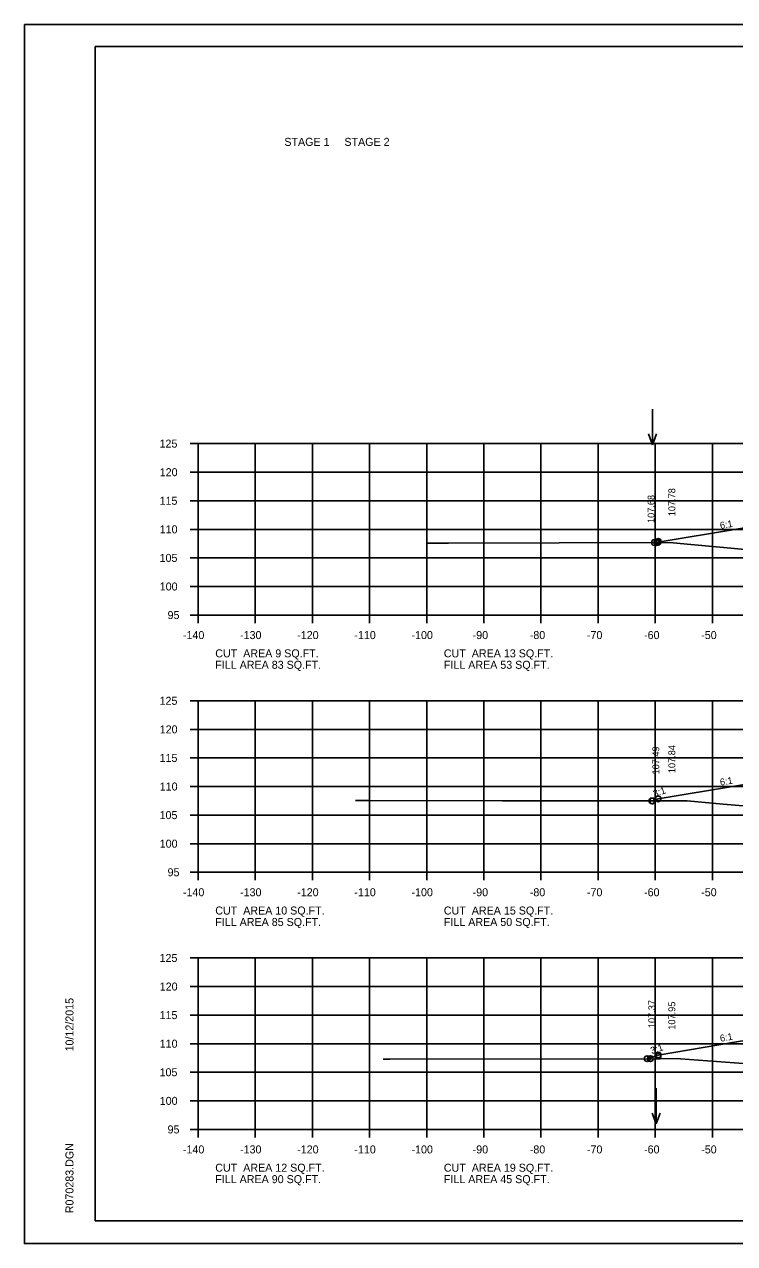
# Model space of a CAD drawing. Extents: x 1175611 to 1176402, y -433344 to -416213.
# Drawn here: x 1175610.6 to 1175734.9, y -428223.4 to -428010.1 of the extents above; entities that cross this region are included whole.
import ezdxf

# ---------------------------------------------------------------- set-up
doc = ezdxf.new("R2010")
doc.units = 0
for name, color, linetype in [('Default', 7, 'Continuous'), ('R_Axis', 7, 'Continuous'), ('R_Axis Annot', 7, 'Continuous'), ('R_Border', 7, 'Continuous'), ('R_Exist Surface', 7, 'Continuous'), ('R_Fin Surface', 7, 'Continuous'), ('R_Grid', 7, 'Continuous'), ('R_No Plot', 7, 'Continuous'), ('R_Water Annot', 7, 'Continuous'), ('R_Xsect Elev', 7, 'Continuous'), ('R_Xsect Slope', 7, 'Continuous')]:
    doc.layers.add(name, color=color, linetype=linetype)

msp = doc.modelspace()

# ---------------------------------------------------------------- linework, layer by layer
at = {"layer": 'R_Axis'}
for p, q in [((1175639.57, -428083.44), (1175640.97, -428083.44)), ((1175640.97, -428113.44), (1175640.97, -428083.44)), ((1175639.57, -428088.44), (1175640.97, -428088.44)), ((1175639.57, -428093.44), (1175640.97, -428093.44)), ((1175639.57, -428098.44), (1175640.97, -428098.44)), ((1175639.57, -428103.44), (1175640.97, -428103.44)), ((1175639.57, -428108.44), (1175640.97, -428108.44)), ((1175639.57, -428113.44), (1175640.97, -428113.44)), ((1175640.97, -428113.44), (1175920.97, -428113.44)), ((1175640.97, -428114.84), (1175640.97, -428113.44)), ((1175650.97, -428114.84), (1175650.97, -428113.44)), ((1175660.97, -428114.84), (1175660.97, -428113.44)), ((1175670.97, -428114.84), (1175670.97, -428113.44)), ((1175680.97, -428114.84), (1175680.97, -428113.44)), ((1175690.97, -428114.84), (1175690.97, -428113.44)), ((1175700.97, -428114.84), (1175700.97, -428113.44)), ((1175710.97, -428114.84), (1175710.97, -428113.44)), ((1175720.97, -428114.84), (1175720.97, -428113.44)), ((1175730.97, -428114.84), (1175730.97, -428113.44)), ((1175639.57, -428128.44), (1175640.97, -428128.44)), ((1175640.97, -428158.44), (1175640.97, -428128.44)), ((1175639.57, -428133.44), (1175640.97, -428133.44)), ((1175639.57, -428138.44), (1175640.97, -428138.44)), ((1175639.57, -428143.44), (1175640.97, -428143.44)), ((1175639.57, -428148.44), (1175640.97, -428148.44)), ((1175639.57, -428153.44), (1175640.97, -428153.44)), ((1175639.57, -428158.44), (1175640.97, -428158.44)), ((1175640.97, -428158.44), (1175920.97, -428158.44)), ((1175640.97, -428159.84), (1175640.97, -428158.44)), ((1175650.97, -428159.84), (1175650.97, -428158.44)), ((1175660.97, -428159.84), (1175660.97, -428158.44)), ((1175670.97, -428159.84), (1175670.97, -428158.44)), ((1175680.97, -428159.84), (1175680.97, -428158.44)), ((1175690.97, -428159.84), (1175690.97, -428158.44)), ((1175700.97, -428159.84), (1175700.97, -428158.44)), ((1175710.97, -428159.84), (1175710.97, -428158.44)), ((1175720.97, -428159.84), (1175720.97, -428158.44)), ((1175730.97, -428159.84), (1175730.97, -428158.44)), ((1175639.57, -428173.44), (1175640.97, -428173.44)), ((1175640.97, -428203.44), (1175640.97, -428173.44)), ((1175639.57, -428178.44), (1175640.97, -428178.44)), ((1175639.57, -428183.44), (1175640.97, -428183.44)), ((1175639.57, -428188.44), (1175640.97, -428188.44)), ((1175639.57, -428193.44), (1175640.97, -428193.44)), ((1175639.57, -428198.44), (1175640.97, -428198.44)), ((1175639.57, -428203.44), (1175640.97, -428203.44)), ((1175640.97, -428203.44), (1175920.97, -428203.44)), ((1175640.97, -428204.84), (1175640.97, -428203.44)), ((1175650.97, -428204.84), (1175650.97, -428203.44)), ((1175660.97, -428204.84), (1175660.97, -428203.44)), ((1175670.97, -428204.84), (1175670.97, -428203.44)), ((1175680.97, -428204.84), (1175680.97, -428203.44)), ((1175690.97, -428204.84), (1175690.97, -428203.44)), ((1175700.97, -428204.84), (1175700.97, -428203.44)), ((1175710.97, -428204.84), (1175710.97, -428203.44)), ((1175720.97, -428204.84), (1175720.97, -428203.44)), ((1175730.97, -428204.84), (1175730.97, -428203.44))]:
    msp.add_line(p, q, dxfattribs=at)
at = {"layer": 'R_Border'}
for p, q in [((1175622.97, -428013.98), (1175939.15, -428013.98)), ((1175622.97, -428219.44), (1175622.97, -428013.98)), ((1175622.97, -428219.44), (1175622.97, -428219.44)), ((1175939.15, -428219.44), (1175622.97, -428219.44))]:
    msp.add_line(p, q, dxfattribs=at)
at = {"layer": 'R_Exist Surface'}
for points in [[(1175680.97, -428100.86), (1175683.75, -428100.86), (1175683.81, -428100.86), (1175684.78, -428100.85), (1175723.5, -428100.76), (1175726.54, -428101.03), (1175737.33, -428102)], [(1175668.53, -428145.86), (1175669.76, -428145.87), (1175670.85, -428145.87), (1175694.26, -428145.92), (1175726.57, -428145.95), (1175732.83, -428146.53), (1175738.48, -428147.02)], [(1175673.33, -428191.17), (1175673.85, -428191.17), (1175674.52, -428191.17), (1175721.8, -428191.06), (1175724.8, -428191.05), (1175725.38, -428191.09), (1175739.54, -428192.12)]]:
    msp.add_lwpolyline(points, dxfattribs=at)
at = {"layer": 'R_Fin Surface'}
for points in [[(1175721.26, -428100.76), (1175721.47, -428100.69), (1175735.2, -428098.4), (1175743.47, -428097.03), (1175749.47, -428096.79), (1175751.47, -428096.75), (1175780.97, -428096.16), (1175810.47, -428096.75), (1175812.47, -428096.79), (1175818.47, -428097.03), (1175823.75, -428098.34), (1175840.45, -428102.32), (1175844.7, -428101.12)], [(1175720.47, -428145.95), (1175721.47, -428145.61), (1175735.2, -428143.32), (1175743.47, -428141.94), (1175749.47, -428141.7), (1175751.47, -428141.66), (1175780.97, -428141.07), (1175810.47, -428141.66), (1175812.47, -428141.7), (1175818.47, -428141.94), (1175823.75, -428143.26), (1175840.47, -428147.44), (1175844.79, -428146.01)], [(1175719.55, -428191.06), (1175721.47, -428190.42), (1175735.2, -428188.14), (1175743.47, -428186.76), (1175749.47, -428186.52), (1175751.47, -428186.48), (1175780.97, -428185.89), (1175810.47, -428186.48), (1175812.47, -428186.52), (1175818.47, -428186.76), (1175823.75, -428188.08), (1175840.47, -428192.26), (1175841.18, -428192.49), (1175845.12, -428191.18)]]:
    msp.add_lwpolyline(points, dxfattribs=at)
at = {"layer": 'R_Grid'}
for p, q in [((1175640.97, -428083.44), (1175920.97, -428083.44)), ((1175640.97, -428113.44), (1175640.97, -428083.44)), ((1175650.97, -428113.44), (1175650.97, -428083.44)), ((1175660.97, -428113.44), (1175660.97, -428083.44)), ((1175670.97, -428113.44), (1175670.97, -428083.44)), ((1175680.97, -428113.44), (1175680.97, -428083.44)), ((1175690.97, -428113.44), (1175690.97, -428083.44)), ((1175700.97, -428113.44), (1175700.97, -428083.44)), ((1175710.97, -428113.44), (1175710.97, -428083.44)), ((1175720.97, -428113.44), (1175720.97, -428083.44)), ((1175730.97, -428113.44), (1175730.97, -428083.44)), ((1175640.97, -428088.44), (1175920.97, -428088.44)), ((1175640.97, -428093.44), (1175920.97, -428093.44)), ((1175640.97, -428098.44), (1175920.97, -428098.44)), ((1175640.97, -428103.44), (1175920.97, -428103.44)), ((1175640.97, -428108.44), (1175920.97, -428108.44)), ((1175640.97, -428113.44), (1175920.97, -428113.44)), ((1175640.97, -428128.44), (1175920.97, -428128.44)), ((1175640.97, -428158.44), (1175640.97, -428128.44)), ((1175650.97, -428158.44), (1175650.97, -428128.44)), ((1175660.97, -428158.44), (1175660.97, -428128.44)), ((1175670.97, -428158.44), (1175670.97, -428128.44)), ((1175680.97, -428158.44), (1175680.97, -428128.44)), ((1175690.97, -428158.44), (1175690.97, -428128.44)), ((1175700.97, -428158.44), (1175700.97, -428128.44)), ((1175710.97, -428158.44), (1175710.97, -428128.44)), ((1175720.97, -428158.44), (1175720.97, -428128.44)), ((1175730.97, -428158.44), (1175730.97, -428128.44)), ((1175640.97, -428133.44), (1175920.97, -428133.44)), ((1175640.97, -428138.44), (1175920.97, -428138.44)), ((1175640.97, -428143.44), (1175920.97, -428143.44)), ((1175640.97, -428148.44), (1175920.97, -428148.44)), ((1175640.97, -428153.44), (1175920.97, -428153.44)), ((1175640.97, -428158.44), (1175920.97, -428158.44)), ((1175640.97, -428173.44), (1175920.97, -428173.44)), ((1175640.97, -428203.44), (1175640.97, -428173.44)), ((1175650.97, -428203.44), (1175650.97, -428173.44)), ((1175660.97, -428203.44), (1175660.97, -428173.44)), ((1175670.97, -428203.44), (1175670.97, -428173.44)), ((1175680.97, -428203.44), (1175680.97, -428173.44)), ((1175690.97, -428203.44), (1175690.97, -428173.44)), ((1175700.97, -428203.44), (1175700.97, -428173.44)), ((1175710.97, -428203.44), (1175710.97, -428173.44)), ((1175720.97, -428203.44), (1175720.97, -428173.44)), ((1175730.97, -428203.44), (1175730.97, -428173.44)), ((1175640.97, -428178.44), (1175920.97, -428178.44)), ((1175640.97, -428183.44), (1175920.97, -428183.44)), ((1175640.97, -428188.44), (1175920.97, -428188.44)), ((1175640.97, -428193.44), (1175920.97, -428193.44)), ((1175640.97, -428198.44), (1175920.97, -428198.44)), ((1175640.97, -428203.44), (1175920.97, -428203.44))]:
    msp.add_line(p, q, dxfattribs=at)
at = {"layer": 'R_No Plot'}
for p, q in [((1175610.57, -428010.08), (1175943.91, -428010.08)), ((1175610.57, -428223.42), (1175943.91, -428223.42))]:
    msp.add_line(p, q, dxfattribs=at)
msp.add_lwpolyline([(1175610.57, -428010.08), (1175943.91, -428010.08), (1175943.91, -428223.42), (1175610.57, -428223.42)], close=True, dxfattribs=at)
for centre in [(1175720.81, -428100.76), (1175721.26, -428100.76), (1175721.26, -428100.76), (1175721.47, -428100.54), (1175721.47, -428100.69), (1175721.47, -428145.58), (1175720.36, -428145.95), (1175720.47, -428145.95), (1175720.47, -428145.95), (1175721.47, -428145.61), (1175719.55, -428191.06), (1175719.55, -428191.06), (1175720.11, -428191.06), (1175721.47, -428190.42), (1175721.47, -428190.61)]:
    msp.add_circle(centre, 0.5, dxfattribs=at)
at = {"layer": 'R_Water Annot'}
for p, q in [((1175720.5, -428077.39), (1175720.5, -428083.67)), ((1175720.5, -428083.67), (1175719.8, -428081.75)), ((1175720.5, -428083.67), (1175721.2, -428081.75)), ((1175721.12, -428196.21), (1175721.12, -428202.49)), ((1175721.12, -428202.49), (1175720.42, -428200.57)), ((1175721.12, -428202.49), (1175721.82, -428200.57))]:
    msp.add_line(p, q, dxfattribs=at)

# ---------------------------------------------------------------- texts
at = {"layer": 'Default'}
for s, p in [('STAGE 1     STAGE 2', (1175656.06, -428031.34)), ('CUT  AREA 9 SQ.FT.', (1175643.97, -428120.84)), ('CUT  AREA 13 SQ.FT.', (1175683.97, -428120.84)), ('FILL AREA 83 SQ.FT.', (1175643.97, -428122.84)), ('FILL AREA 53 SQ.FT.', (1175683.97, -428122.84)), ('CUT  AREA 10 SQ.FT.', (1175643.97, -428165.84)), ('FILL AREA 85 SQ.FT.', (1175643.97, -428167.84)), ('CUT  AREA 15 SQ.FT.', (1175683.97, -428165.84)), ('FILL AREA 50 SQ.FT.', (1175683.97, -428167.84)), ('CUT  AREA 12 SQ.FT.', (1175643.97, -428210.84)), ('CUT  AREA 19 SQ.FT.', (1175683.97, -428210.84)), ('FILL AREA 90 SQ.FT.', (1175643.97, -428212.84)), ('FILL AREA 45 SQ.FT.', (1175683.97, -428212.84))]:
    msp.add_text(s, height=1.4, dxfattribs=at).set_placement(p)
at = {"layer": 'R_Axis Annot'}
for s, p in [('125', (1175634.22, -428084.14)), ('120', (1175634.25, -428089.14)), ('115', (1175634.22, -428094.14)), ('110', (1175634.25, -428099.14)), ('105', (1175634.22, -428104.14)), ('100', (1175634.25, -428109.14)), ('95', (1175635.62, -428114.14)), ('-140', (1175638.31, -428117.64)), ('-130', (1175648.31, -428117.64)), ('-120', (1175658.31, -428117.64)), ('-110', (1175668.31, -428117.64)), ('-100', (1175678.31, -428117.64)), ('-90', (1175689.01, -428117.64)), ('-80', (1175699.01, -428117.64)), ('-70', (1175709.01, -428117.64)), ('-60', (1175719.01, -428117.64)), ('-50', (1175729.01, -428117.64)), ('125', (1175634.22, -428129.14)), ('120', (1175634.25, -428134.14)), ('115', (1175634.22, -428139.14)), ('110', (1175634.25, -428144.14)), ('105', (1175634.22, -428149.14)), ('100', (1175634.25, -428154.14)), ('95', (1175635.62, -428159.14)), ('-140', (1175638.31, -428162.64)), ('-130', (1175648.31, -428162.64)), ('-120', (1175658.31, -428162.64)), ('-110', (1175668.31, -428162.64)), ('-100', (1175678.31, -428162.64)), ('-90', (1175689.01, -428162.64)), ('-80', (1175699.01, -428162.64)), ('-70', (1175709.01, -428162.64)), ('-60', (1175719.01, -428162.64)), ('-50', (1175729.01, -428162.64)), ('125', (1175634.22, -428174.14)), ('120', (1175634.25, -428179.14)), ('115', (1175634.22, -428184.14)), ('110', (1175634.25, -428189.14)), ('105', (1175634.22, -428194.14)), ('100', (1175634.25, -428199.14)), ('95', (1175635.62, -428204.14)), ('-140', (1175638.31, -428207.64)), ('-130', (1175648.31, -428207.64)), ('-120', (1175658.31, -428207.64)), ('-110', (1175668.31, -428207.64)), ('-100', (1175678.31, -428207.64)), ('-90', (1175689.01, -428207.64)), ('-80', (1175699.01, -428207.64)), ('-70', (1175709.01, -428207.64)), ('-60', (1175719.01, -428207.64)), ('-50', (1175729.01, -428207.64))]:
    msp.add_text(s, height=1.4, dxfattribs=at).set_placement(p)
at = {"layer": 'R_Border'}
for s, p in [('10/12/2015', (1175619.16, -428189.8)), ('R070283.DGN', (1175619.16, -428218.11))]:
    msp.add_text(s, height=1.4, rotation=90, dxfattribs=at).set_placement(p)
at = {"layer": 'R_Xsect Elev'}
for s, p in [('107.78', (1175724.47, -428096.15)), ('107.68', (1175720.84, -428097.33)), ('107.49', (1175721.67, -428141.33)), ('107.84', (1175724.47, -428141.1)), ('107.37', (1175720.96, -428185.71)), ('107.95', (1175724.47, -428185.99))]:
    msp.add_text(s, height=1.2, rotation=90, dxfattribs=at).set_placement(p)
at = {"layer": 'R_Xsect Slope'}
for s, rotation, p in [('6:1', 9.4623, (1175732.39, -428098.37)), ('6:1', 9.4623, (1175732.39, -428143.29)), ('3:1', 18.4349, (1175720.81, -428145.31)), ('6:1', 9.4623, (1175732.39, -428188.1)), ('3:1', 18.4349, (1175720.35, -428190.27))]:
    msp.add_text(s, height=1.2, rotation=rotation, dxfattribs=at).set_placement(p)

doc.saveas('drawing.dxf')
